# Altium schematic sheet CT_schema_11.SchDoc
size 742 x 377 mm
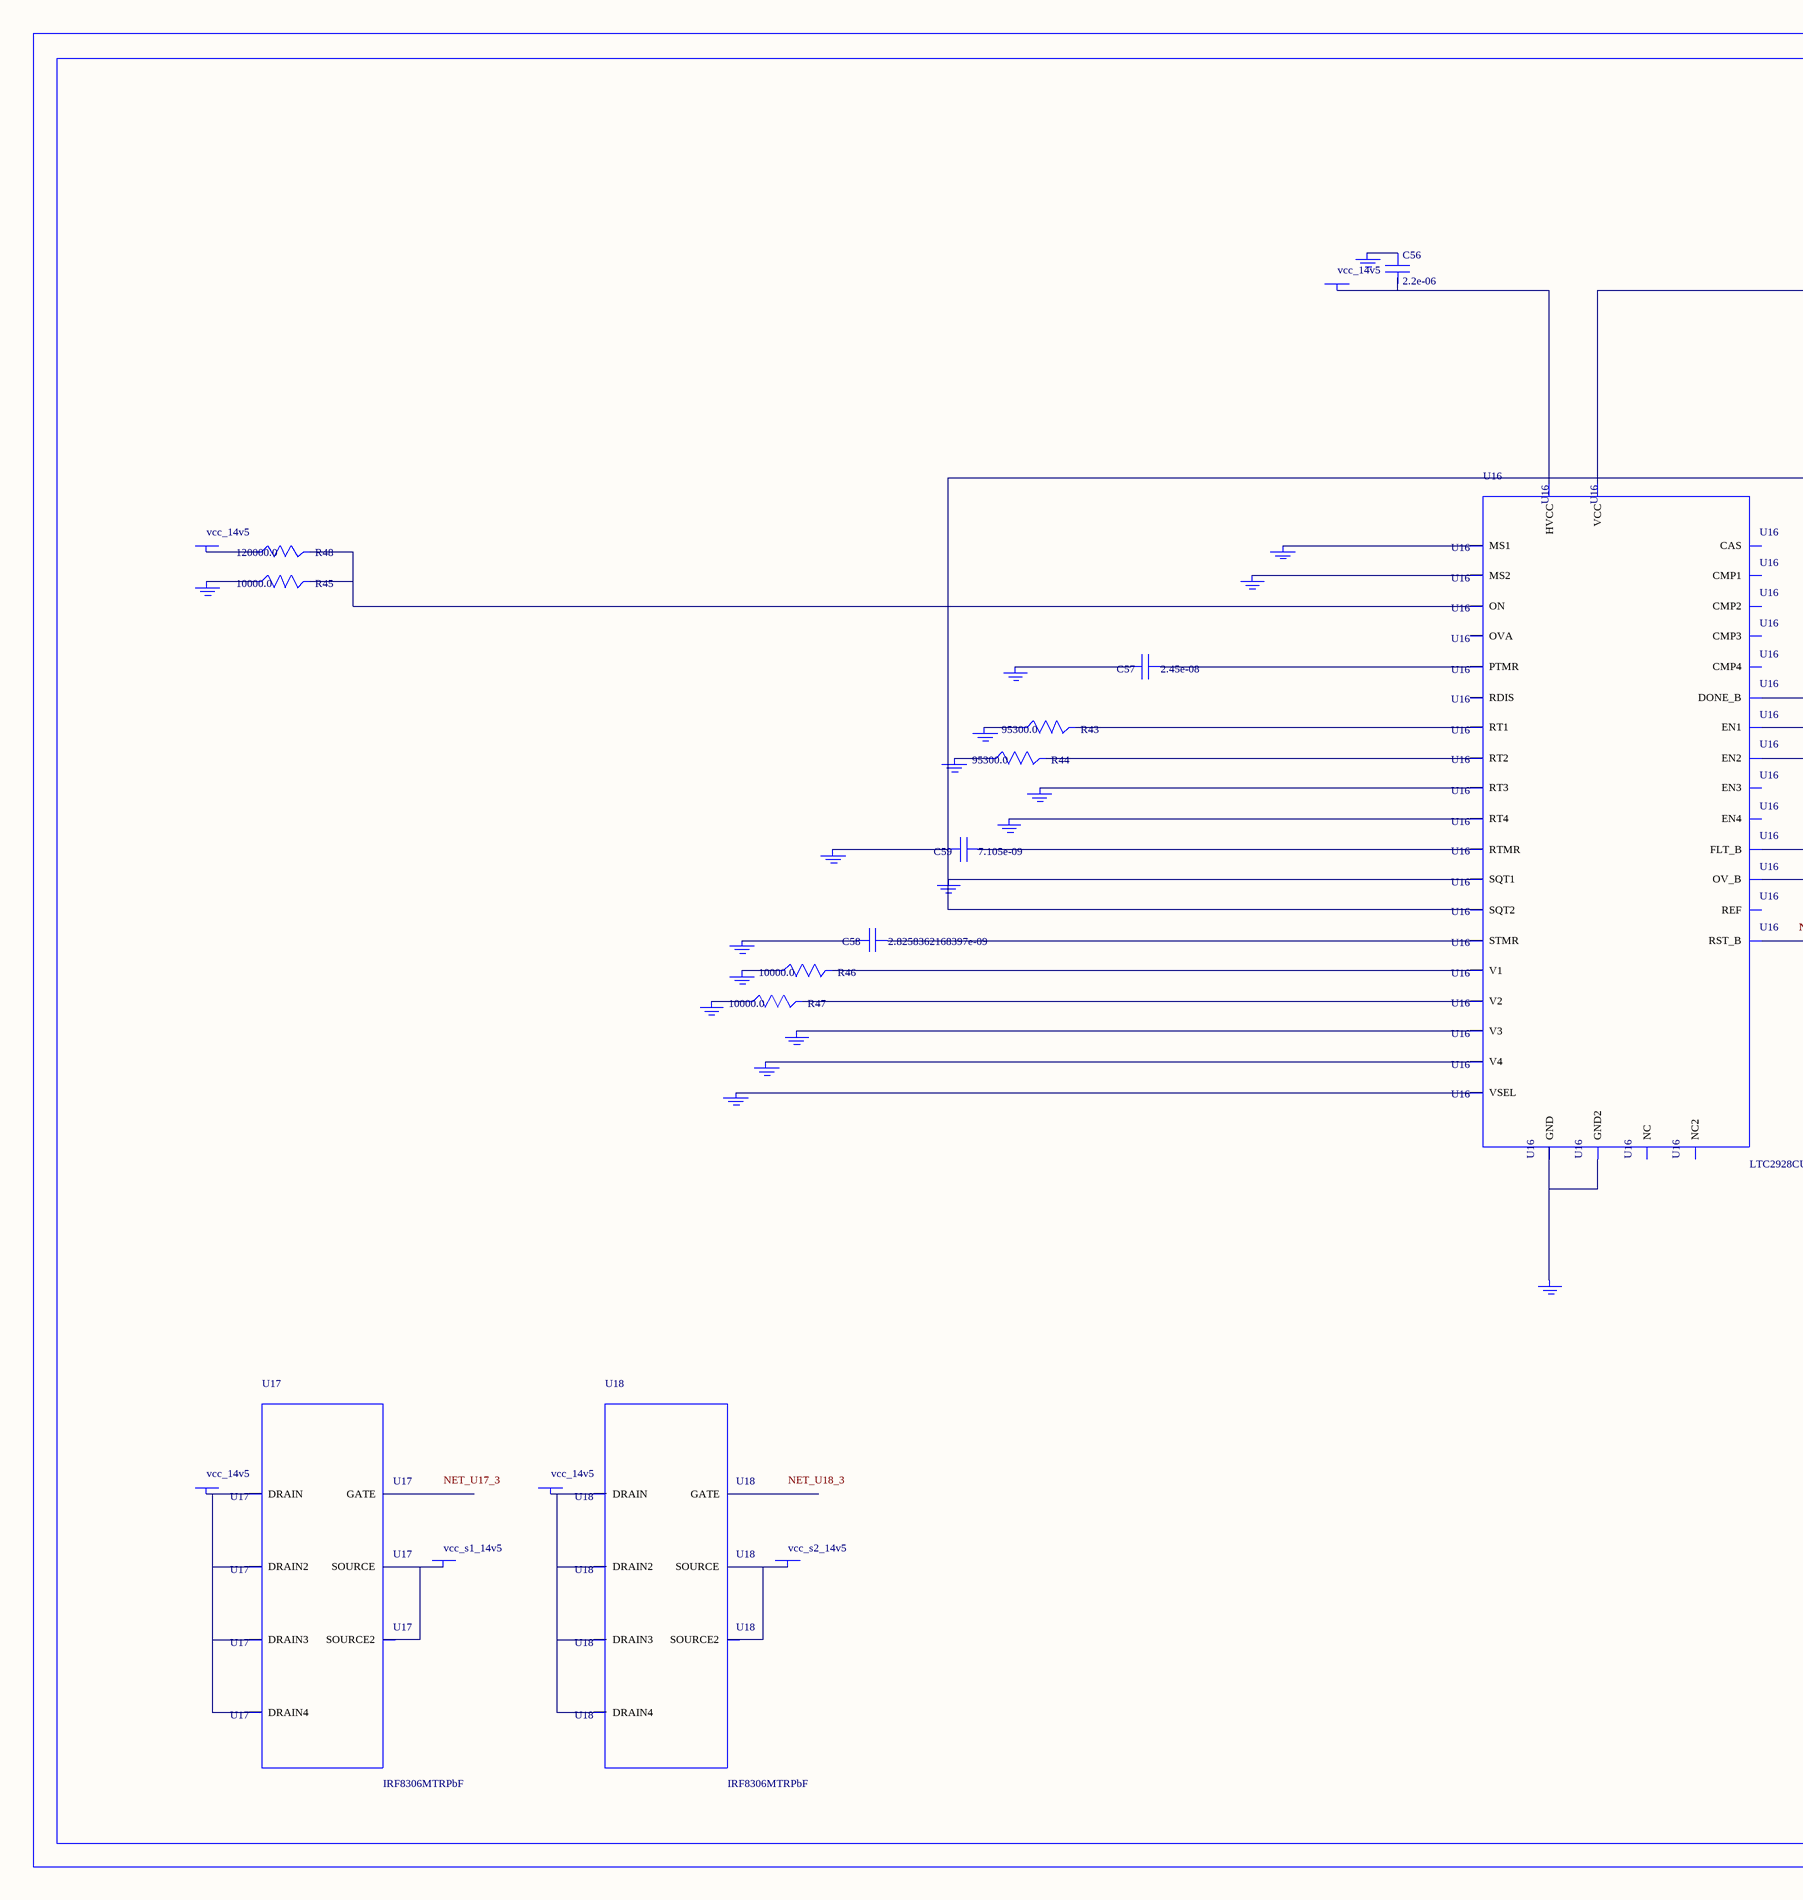
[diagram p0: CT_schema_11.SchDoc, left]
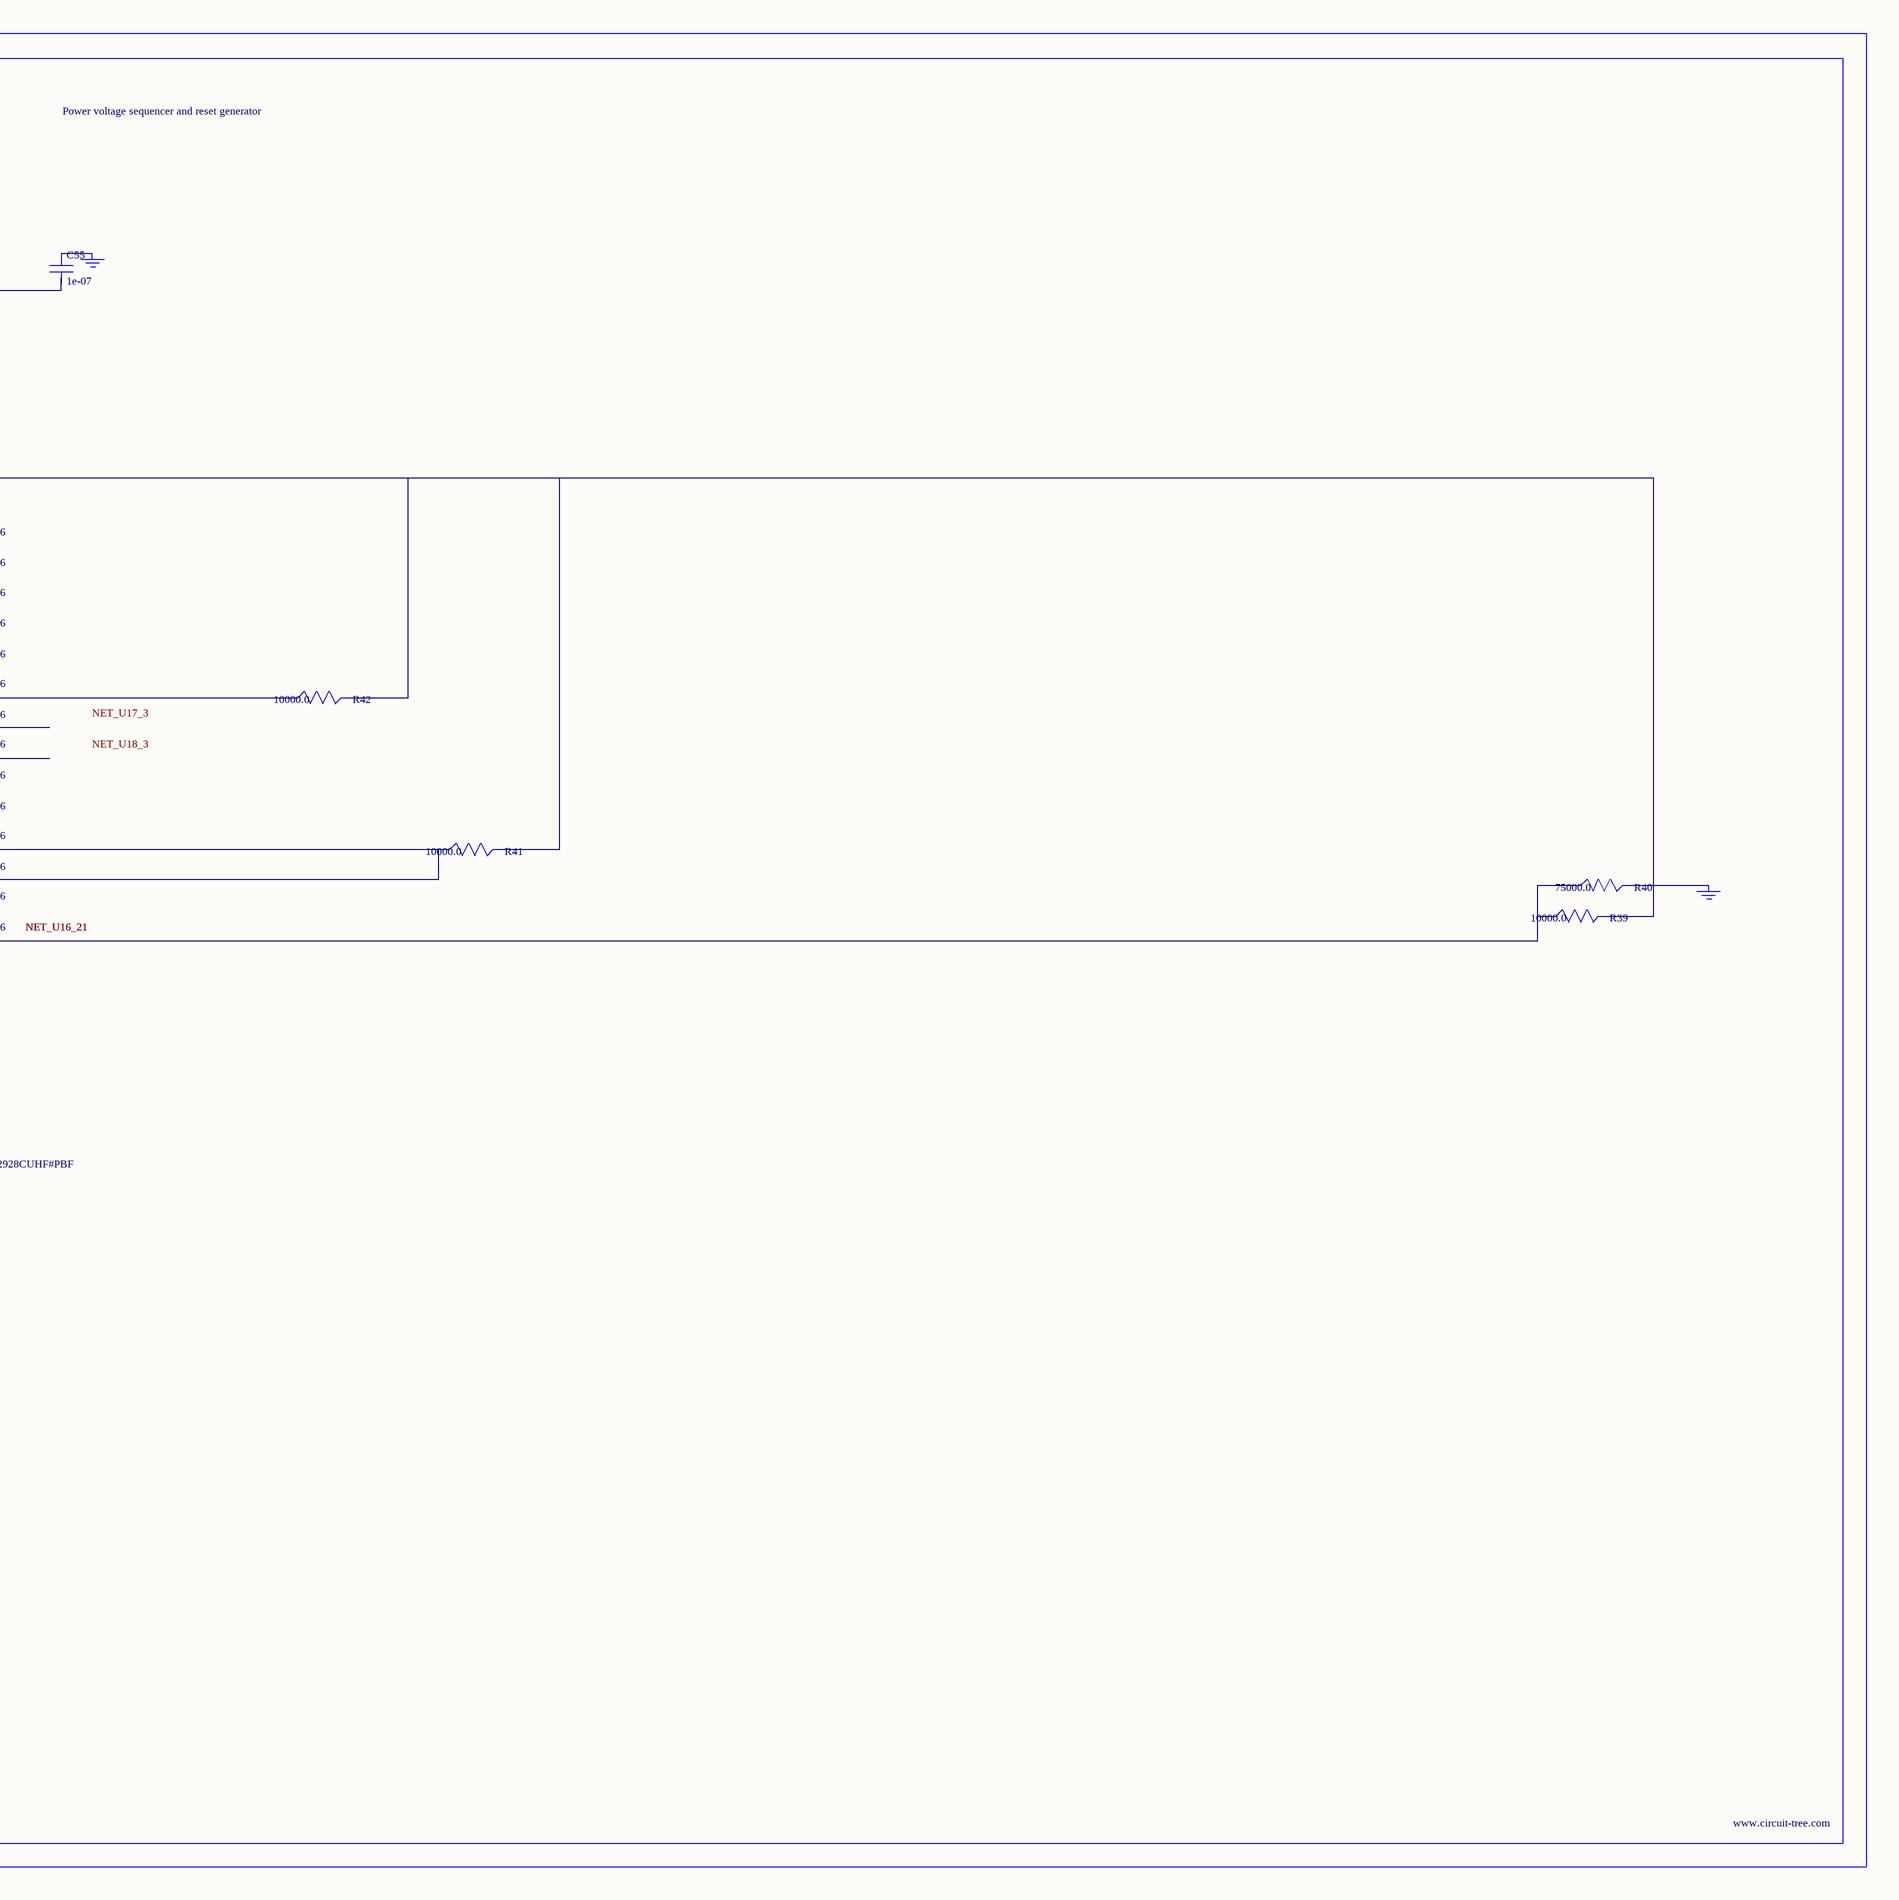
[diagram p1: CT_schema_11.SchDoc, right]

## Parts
BORDER10  (no value)
C55  1e-07  [C0402]
C56  2.2e-06  [C0603]
C57  2.45e-08  [R0603]
C58  2.8258362168397e-09  [R0603]
C59  7.105e-09  [R0603]
GND_INSTANCE_10_0  (no value)
GND_INSTANCE_10_1  (no value)
GND_INSTANCE_10_2  (no value)
GND_INSTANCE_10_3  (no value)
GND_INSTANCE_10_4  (no value)
GND_INSTANCE_10_5  (no value)
GND_INSTANCE_10_6  (no value)
GND_INSTANCE_10_7  (no value)
GND_INSTANCE_10_8  (no value)
GND_INSTANCE_10_9  (no value)
GND_INSTANCE_10_10  (no value)
GND_INSTANCE_10_11  (no value)
GND_INSTANCE_10_12  (no value)
GND_INSTANCE_10_13  (no value)
GND_INSTANCE_10_14  (no value)
GND_INSTANCE_10_15  (no value)
GND_INSTANCE_10_16  (no value)
GND_INSTANCE_10_17  (no value)
GND_INSTANCE_10_18  (no value)
GND_INSTANCE_10_19  (no value)
POWER_INSTANCE_10_0  vcc_14v5
POWER_INSTANCE_10_1  vcc_14v5
POWER_INSTANCE_10_2  vcc_14v5
POWER_INSTANCE_10_3  vcc_s1_14v5
POWER_INSTANCE_10_4  vcc_14v5
POWER_INSTANCE_10_5  vcc_s2_14v5
R39  10000.0  [R0603]
R40  75000.0  [R0603]
R41  10000.0  [R0603]
R42  10000.0  [R0603]
R43  95300.0  [R0603]
R44  95300.0  [R0603]
R45  10000.0  [R0603]
R46  10000.0  [R0603]
R47  10000.0  [R0603]
R48  120000.0  [R0603]
U16  LTC2928CUHF#PBF  [QFN-38_UHF]
U17  IRF8306MTRPbF  [IRF8306MTRPBF]
U18  IRF8306MTRPbF  [IRF8306MTRPBF]

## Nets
NetC55_1: C55.1 GND_INSTANCE_10_10.0(GND)
NetC55_2: C55.2 C59.2 GND_INSTANCE_10_5.0(GND) GND_INSTANCE_10_15.0(GND) R39.2 R41.2 R42.2 U16.10(SQT1) U16.11(SQT2) U16.22(VCC)
NetC56_1: C56.1 GND_INSTANCE_10_11.0(GND)
NetC56_2: C56.2 POWER_INSTANCE_10_1.0(PWR) U16.23(HVCC)
NetC57_1: C57.1 U16.27(PTMR)
NetC57_2: C57.2 GND_INSTANCE_10_14.0(GND)
NetC58_1: C58.1 U16.26(STMR)
NetC58_2: C58.2 GND_INSTANCE_10_13.0(GND)
NetC59_1: C59.1 U16.28(RTMR)
NetGND_INSTANCE_10_0_0: GND_INSTANCE_10_0.0(GND) R46.1
NetGND_INSTANCE_10_1_0: GND_INSTANCE_10_1.0(GND) R43.1
NetGND_INSTANCE_10_2_0: GND_INSTANCE_10_2.0(GND) R44.1
NetGND_INSTANCE_10_3_0: GND_INSTANCE_10_3.0(GND) U16.8(RT3)
NetGND_INSTANCE_10_4_0: GND_INSTANCE_10_4.0(GND) U16.9(RT4)
NetGND_INSTANCE_10_6_0: GND_INSTANCE_10_6.0(GND) U16.12(MS1)
NetGND_INSTANCE_10_7_0: GND_INSTANCE_10_7.0(GND) U16.13(MS2)
NetGND_INSTANCE_10_8_0: GND_INSTANCE_10_8.0(GND) R45.1
NetGND_INSTANCE_10_9_0: GND_INSTANCE_10_9.0(GND) R40.2
NetGND_INSTANCE_10_12_0: GND_INSTANCE_10_12.0(GND) U16.25(VSEL)
NetGND_INSTANCE_10_16_0: GND_INSTANCE_10_16.0(GND) U16.30(V4)
NetGND_INSTANCE_10_17_0: GND_INSTANCE_10_17.0(GND) U16.32(V3)
NetGND_INSTANCE_10_18_0: GND_INSTANCE_10_18.0(GND) R47.1
NetGND_INSTANCE_10_19_0: GND_INSTANCE_10_19.0(GND) U16.24(GND) U16.39(GND2)
NetPOWER_INSTANCE_10_0_0: POWER_INSTANCE_10_0.0(PWR) R48.1
NetPOWER_INSTANCE_10_2_0: POWER_INSTANCE_10_2.0(PWR) U17.1(DRAIN) U17.2(DRAIN2) U17.6(DRAIN3) U17.7(DRAIN4)
NetPOWER_INSTANCE_10_3_0: POWER_INSTANCE_10_3.0(PWR) U17.4(SOURCE) U17.5(SOURCE2)
NetPOWER_INSTANCE_10_4_0: POWER_INSTANCE_10_4.0(PWR) U18.1(DRAIN) U18.2(DRAIN2) U18.6(DRAIN3) U18.7(DRAIN4)
NetPOWER_INSTANCE_10_5_0: POWER_INSTANCE_10_5.0(PWR) U18.4(SOURCE) U18.5(SOURCE2)
NetR39_1: R39.1 R40.1 U16.21(RST_B)
NetR41_1: R41.1 U16.19(FLT_B) U16.20(OV_B)
NetR42_1: R42.1 U16.18(DONE_B)
NetR43_2: R43.2 U16.6(RT1)
NetR44_2: R44.2 U16.7(RT2)
NetR45_2: R45.2 R48.2 U16.16(ON)
NetR46_2: R46.2 U16.3(V1)
NetR47_2: R47.2 U16.38(V2)

Not connected (* = marked no-connect by the designer): U16 1(OVA) 2(EN1) 4(NC) 5(REF) 14(RDIS) 15(CAS) 17(NC2) 29(EN4) 31(EN3) 33(CMP3) 34(CMP4) 35(CMP1) 36(CMP2) 37(EN2); U17 3(GATE); U18 3(GATE)

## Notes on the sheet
- Labels drawn without touching a wire or pin: NET_U17_3, NET_U18_3

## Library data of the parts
BORDER10 = BORDER_PAGE10
C55 = C0402C104K3RACTU
C56 = GRM188R61H225KE1115D
C57 = C57
C58 = C58
C59 = C59
GND_INSTANCE_10_0-GND_INSTANCE_10_19 = GND
POWER_INSTANCE_10_0-POWER_INSTANCE_10_5 = PWR
R39 R41 R42 R45-R47 = RC0603JR-0710KL
R40 = RC0603JR-0775KL
R43 R44 = RC0603FR-0795K3L
R48 = RC0603JR-07120KL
